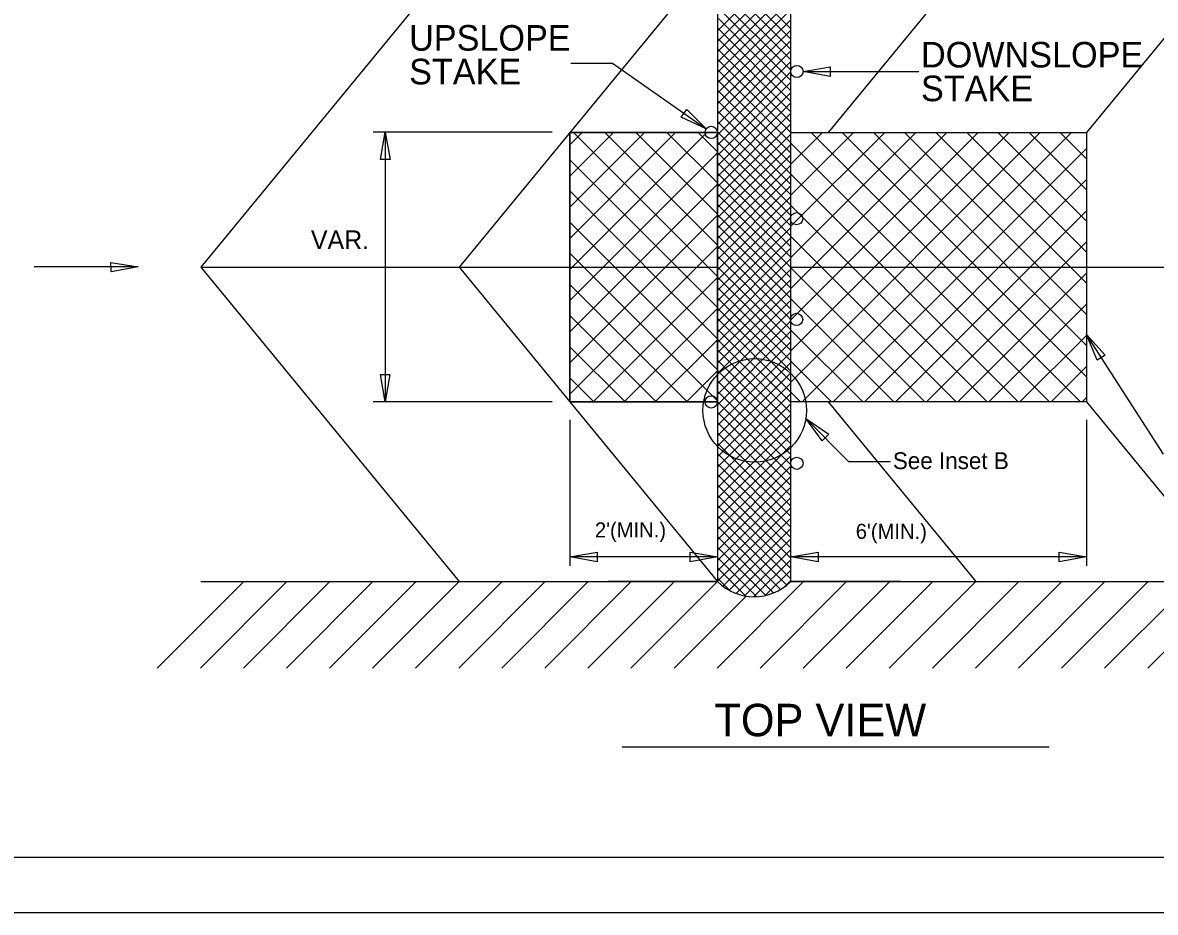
# Model space of a CAD drawing. Extents: x 8096 to 9796, y 9620 to 10720.
# Drawn here: x 9098.7 to 9561.9, y 9619.8 to 9983.4 of the extents above; entities that cross this region are included whole.
import ezdxf

# ---------------------------------------------------------------- set-up
doc = ezdxf.new("R2010")
doc.units = 0
for name, color, linetype in [('Blank Plan Sheet Both CELL', 7, 'Continuous'), ('Default', 7, 'Continuous'), ('Old_Level_1', 7, 'Continuous'), ('Old_Level_2', 7, 'Continuous'), ('Old_Level_20', 7, 'Continuous'), ('Sheet Plot Border Outside CELL', 7, 'Continuous')]:
    doc.layers.add(name, color=color, linetype=linetype)

msp = doc.modelspace()

# ---------------------------------------------------------------- linework, layer by layer
at = {"layer": 'Blank Plan Sheet Both CELL'}
msp.add_lwpolyline([(9762.02, 10692.33), (8262.02, 10692.33), (8262.02, 9642.33), (9762.02, 9642.33)], close=True, dxfattribs=at)
at = {"layer": 'Default'}
for p, q in [((9382.84, 10011.98), (9382.84, 9754.98)), ((9382.84, 10010.95), (9412.86, 9980.94)), ((9382.84, 9979.99), (9412.86, 10010)), ((9412.86, 9754.98), (9412.86, 10011.98)), ((9382.84, 10006.71), (9412.86, 9976.69)), ((9382.84, 9975.74), (9412.86, 10005.76)), ((9382.84, 10002.46), (9412.86, 9972.45)), ((9382.84, 9971.5), (9412.86, 10001.51)), ((9382.84, 9998.22), (9412.86, 9968.21)), ((9382.84, 9967.26), (9412.86, 9997.27)), ((9382.84, 9993.98), (9412.86, 9963.97)), ((9382.84, 9963.02), (9412.86, 9993.03)), ((9382.84, 9989.73), (9412.86, 9959.72)), ((9382.84, 9958.77), (9412.86, 9988.79)), ((9382.84, 9985.49), (9412.86, 9955.48)), ((9382.84, 9954.53), (9412.86, 9984.54)), ((9382.84, 9981.25), (9412.86, 9951.24)), ((9382.84, 9950.29), (9412.86, 9980.3)), ((9382.84, 9977.01), (9412.86, 9946.99)), ((9382.84, 9946.05), (9412.86, 9976.06)), ((9382.84, 9972.76), (9412.86, 9942.75)), ((9382.84, 9941.8), (9412.86, 9971.82)), ((9382.84, 9968.52), (9412.86, 9938.51)), ((9382.84, 9937.56), (9412.86, 9967.57)), ((9382.84, 9964.28), (9412.86, 9934.27)), ((9382.84, 9933.32), (9412.86, 9963.33)), ((9382.84, 9960.04), (9412.86, 9930.02)), ((9382.84, 9929.07), (9412.86, 9959.09)), ((9382.84, 9955.79), (9412.86, 9925.78)), ((9382.84, 9924.83), (9412.86, 9954.84)), ((9382.84, 9951.55), (9412.86, 9921.54)), ((9382.84, 9920.59), (9412.86, 9950.6)), ((9382.84, 9947.31), (9412.86, 9917.3)), ((9382.84, 9916.35), (9412.86, 9946.36)), ((9382.84, 9943.07), (9412.86, 9913.05)), ((9382.84, 9912.1), (9412.86, 9942.12)), ((9322.47, 9828.41), (9322.47, 9938.55)), ((9322.47, 9938.55), (9382.84, 9938.55)), ((9322.47, 9828.41), (9322.47, 9938.55)), ((9322.47, 9938.55), (9322.47, 9828.41)), ((9382.84, 9938.55), (9322.47, 9938.55)), ((9322.47, 9938.55), (9322.47, 9828.41)), ((9322.47, 9933.44), (9327.58, 9938.55)), ((9322.47, 9920.71), (9340.31, 9938.55)), ((9322.47, 9907.99), (9353.04, 9938.55)), ((9322.47, 9895.26), (9365.76, 9938.55)), ((9322.47, 9882.53), (9378.49, 9938.55)), ((9324.01, 9938.55), (9382.84, 9879.72)), ((9336.74, 9938.55), (9382.84, 9892.45)), ((9349.47, 9938.55), (9382.84, 9905.17)), ((9362.2, 9938.55), (9382.84, 9917.9)), ((9374.92, 9938.55), (9382.84, 9930.63)), ((9382.84, 9938.82), (9412.86, 9908.81)), ((9382.84, 9828.41), (9382.84, 9938.55)), ((9382.84, 9907.86), (9412.86, 9937.87)), ((9412.86, 9938.55), (9533.77, 9938.55)), ((9412.86, 9828.41), (9412.86, 9938.55)), ((9412.86, 9938.55), (9533.77, 9938.55)), ((9412.86, 9938.35), (9413.05, 9938.55)), ((9412.86, 9925.63), (9425.78, 9938.55)), ((9412.86, 9912.9), (9438.51, 9938.55)), ((9412.86, 9900.17), (9451.24, 9938.55)), ((9412.86, 9887.44), (9463.96, 9938.55)), ((9412.86, 9874.71), (9476.69, 9938.55)), ((9412.86, 9861.99), (9489.42, 9938.55)), ((9412.86, 9849.26), (9502.15, 9938.55)), ((9412.86, 9836.53), (9514.87, 9938.55)), ((9417.46, 9828.41), (9527.6, 9938.55)), ((9421.2, 9938.55), (9531.34, 9828.41)), ((9433.92, 9938.55), (9533.77, 9838.7)), ((9446.65, 9938.55), (9533.77, 9851.43)), ((9459.38, 9938.55), (9533.77, 9864.16)), ((9472.11, 9938.55), (9533.77, 9876.89)), ((9484.84, 9938.55), (9533.77, 9889.62)), ((9497.56, 9938.55), (9533.77, 9902.34)), ((9510.29, 9938.55), (9533.77, 9915.07)), ((9523.02, 9938.55), (9533.77, 9927.8)), ((9533.77, 9938.55), (9533.77, 9828.41)), ((9533.77, 9938.55), (9533.77, 9828.41)), ((9382.84, 9934.58), (9412.86, 9904.57)), ((9382.84, 9903.62), (9412.86, 9933.63)), ((9412.86, 9934.16), (9518.61, 9828.41)), ((9430.19, 9828.41), (9533.77, 9931.99)), ((9322.47, 9869.8), (9382.84, 9930.17)), ((9322.47, 9927.36), (9382.84, 9866.99)), ((9382.84, 9930.34), (9412.86, 9900.33)), ((9382.84, 9899.38), (9412.86, 9929.39)), ((9382.84, 9926.1), (9412.86, 9896.08)), ((9382.84, 9895.13), (9412.86, 9925.15)), ((9382.84, 9921.85), (9412.86, 9891.84)), ((9412.86, 9921.44), (9505.88, 9828.41)), ((9322.47, 9857.07), (9382.84, 9917.44)), ((9382.84, 9890.89), (9412.86, 9920.9)), ((9382.84, 9917.61), (9412.86, 9887.6)), ((9442.92, 9828.41), (9533.77, 9919.26)), ((9322.47, 9914.63), (9382.84, 9854.26)), ((9382.84, 9886.65), (9412.86, 9916.66)), ((9382.84, 9913.37), (9412.86, 9883.36)), ((9382.84, 9882.41), (9412.86, 9912.42)), ((9382.84, 9909.12), (9412.86, 9879.11)), ((9382.84, 9878.16), (9412.86, 9908.18)), ((9412.86, 9908.71), (9493.16, 9828.41)), ((9322.47, 9844.35), (9382.84, 9904.72)), ((9382.84, 9904.88), (9412.86, 9874.87)), ((9382.84, 9873.92), (9412.86, 9903.93)), ((9455.64, 9828.41), (9533.77, 9906.53)), ((9322.47, 9901.91), (9382.84, 9841.53)), ((9382.84, 9900.64), (9412.86, 9870.63)), ((9382.84, 9869.68), (9412.86, 9899.69)), ((9382.84, 9896.4), (9412.86, 9866.38)), ((9382.84, 9865.44), (9412.86, 9895.45)), ((9412.86, 9895.98), (9480.43, 9828.41)), ((9468.37, 9828.41), (9533.77, 9893.81)), ((9322.47, 9831.62), (9382.84, 9891.99)), ((9322.47, 9889.18), (9382.84, 9828.81)), ((9382.84, 9892.15), (9412.86, 9862.14)), ((9382.84, 9861.19), (9412.86, 9891.2)), ((9382.84, 9887.91), (9412.86, 9857.9)), ((9382.84, 9856.95), (9412.86, 9886.96)), ((9382.84, 9883.67), (9412.86, 9853.66)), ((9382.84, 9852.71), (9412.86, 9882.72)), ((9412.86, 9883.25), (9467.7, 9828.41)), ((9481.1, 9828.41), (9533.77, 9881.08)), ((9322.47, 9876.45), (9370.52, 9828.41)), ((9331.99, 9828.41), (9382.84, 9879.26)), ((9382.84, 9879.43), (9412.86, 9849.41)), ((9382.84, 9848.46), (9412.86, 9878.48)), ((9382.84, 9875.18), (9412.86, 9845.17)), ((9382.84, 9844.22), (9412.86, 9874.23)), ((9382.84, 9870.94), (9412.86, 9840.93)), ((9412.86, 9870.52), (9454.97, 9828.41)), ((9344.72, 9828.41), (9382.84, 9866.53)), ((9382.84, 9839.98), (9412.86, 9869.99)), ((9382.84, 9866.7), (9412.86, 9836.69)), ((9382.84, 9835.74), (9412.86, 9865.75)), ((9493.83, 9828.41), (9533.77, 9868.35)), ((9322.47, 9863.72), (9357.79, 9828.41)), ((9382.84, 9862.46), (9412.86, 9832.44)), ((9382.84, 9831.49), (9412.86, 9861.51)), ((9382.84, 9858.21), (9412.86, 9828.2)), ((9382.84, 9827.25), (9412.86, 9857.26)), ((9412.86, 9857.8), (9442.24, 9828.41)), ((9357.44, 9828.41), (9382.84, 9853.81)), ((9382.84, 9853.97), (9412.86, 9823.96)), ((9382.84, 9823.01), (9412.86, 9853.02)), ((9506.56, 9828.41), (9533.77, 9855.62)), ((9322.47, 9850.99), (9345.06, 9828.41)), ((9382.84, 9849.73), (9412.86, 9819.72)), ((9382.84, 9818.77), (9412.86, 9848.78)), ((9382.84, 9845.49), (9412.86, 9815.47)), ((9382.84, 9814.52), (9412.86, 9844.54)), ((9412.86, 9845.07), (9429.52, 9828.41)), ((9519.28, 9828.41), (9533.77, 9842.89)), ((9322.47, 9838.27), (9332.33, 9828.41)), ((9370.17, 9828.41), (9382.84, 9841.08)), ((9382.84, 9841.24), (9412.86, 9811.23)), ((9382.84, 9810.28), (9412.86, 9840.29)), ((9382.84, 9837), (9412.86, 9806.99)), ((9382.84, 9806.04), (9412.86, 9836.05)), ((9382.84, 9832.76), (9412.86, 9802.74)), ((9382.84, 9801.8), (9412.86, 9831.81)), ((9412.86, 9832.34), (9416.79, 9828.41)), ((9532.01, 9828.41), (9533.77, 9830.17)), ((9382.84, 9828.41), (9322.47, 9828.41)), ((9322.47, 9828.41), (9382.84, 9828.41)), ((9382.84, 9828.51), (9412.86, 9798.5)), ((9382.84, 9797.55), (9412.86, 9827.57)), ((9382.84, 9824.27), (9412.86, 9794.26)), ((9533.77, 9828.41), (9412.86, 9828.41)), ((9533.77, 9828.41), (9412.86, 9828.41)), ((9382.84, 9793.31), (9412.86, 9823.32)), ((9382.84, 9820.03), (9412.86, 9790.02)), ((9382.84, 9789.07), (9412.86, 9819.08)), ((9382.84, 9815.79), (9412.86, 9785.77)), ((9382.84, 9784.83), (9412.86, 9814.84)), ((9382.84, 9811.54), (9412.86, 9781.53)), ((9382.84, 9780.58), (9412.86, 9810.59)), ((9382.84, 9807.3), (9412.86, 9777.29)), ((9382.84, 9776.34), (9412.86, 9806.35)), ((9382.84, 9803.06), (9412.86, 9773.05)), ((9382.84, 9772.1), (9412.86, 9802.11)), ((9382.84, 9798.82), (9412.86, 9768.8)), ((9382.84, 9767.85), (9412.86, 9797.87)), ((9382.84, 9794.57), (9412.86, 9764.56)), ((9382.84, 9763.61), (9412.86, 9793.62)), ((9382.84, 9790.33), (9412.86, 9760.32)), ((9382.84, 9759.37), (9412.86, 9789.38)), ((9382.84, 9786.09), (9412.86, 9756.08)), ((9382.84, 9755.13), (9412.86, 9785.14)), ((9382.84, 9781.85), (9411.17, 9753.52)), ((9385.06, 9753.11), (9412.86, 9780.9)), ((9382.84, 9777.6), (9408.65, 9751.79)), ((9382.84, 9773.36), (9405.82, 9750.38)), ((9387.65, 9751.45), (9412.86, 9776.65)), ((9382.84, 9769.12), (9402.57, 9749.39)), ((9390.57, 9750.12), (9412.86, 9772.41)), ((9382.84, 9764.87), (9398.84, 9748.88)), ((9393.92, 9749.23), (9412.86, 9768.17)), ((9397.79, 9748.86), (9412.86, 9763.93)), ((9382.84, 9760.63), (9394.32, 9749.15)), ((9402.57, 9749.39), (9412.86, 9759.68)), ((9189.15, 9754.98), (9153.8, 9719.62)), ((9206.76, 9754.98), (9171.41, 9719.62)), ((9224.37, 9754.98), (9189.01, 9719.62)), ((9241.98, 9754.98), (9206.62, 9719.62)), ((9259.59, 9754.98), (9224.23, 9719.62)), ((9277.19, 9754.98), (9241.84, 9719.62)), ((9294.8, 9754.98), (9259.45, 9719.62)), ((9312.41, 9754.98), (9277.05, 9719.62)), ((9330.02, 9754.98), (9294.66, 9719.62)), ((9347.63, 9754.98), (9312.27, 9719.62)), ((9365.23, 9754.98), (9329.88, 9719.62)), ((9382.84, 9754.98), (9347.49, 9719.62)), ((9418.06, 9754.98), (9382.7, 9719.62)), ((9382.84, 9756.39), (9387.94, 9751.29)), ((9435.67, 9754.98), (9400.31, 9719.62)), ((9410.17, 9752.76), (9412.86, 9755.44)), ((9453.28, 9754.98), (9417.92, 9719.62)), ((9470.88, 9754.98), (9435.53, 9719.62)), ((9488.49, 9754.98), (9453.14, 9719.62)), ((9506.1, 9754.98), (9470.75, 9719.62)), ((9523.71, 9754.98), (9488.35, 9719.62)), ((9541.32, 9754.98), (9505.96, 9719.62)), ((9558.93, 9754.98), (9523.57, 9719.62)), ((9576.53, 9754.98), (9541.18, 9719.62)), ((9594.14, 9754.98), (9558.79, 9719.62)), ((9394.56, 9749.09), (9365.1, 9719.62))]:
    msp.add_line(p, q, dxfattribs=at)
for points in [[(9277.19, 10011.98), (9171.54, 9883.48), (9277.19, 9754.98)], [(9382.84, 10011.98), (9277.19, 9883.48), (9382.84, 9754.98)], [(9488.49, 10011.98), (9428.12, 9938.55)], [(9594.14, 10011.98), (9533.77, 9938.55)], [(9428.12, 9828.41), (9488.49, 9754.98)], [(9533.77, 9828.41), (9594.14, 9754.98)]]:
    msp.add_lwpolyline(points, dxfattribs=at)
for centre, radius in [((9415.35, 9963.43), 2.5), ((9380.34, 9938.55), 2.5), ((9415.23, 9903.29), 2.5), ((9415.23, 9862.12), 2.5), ((9398.1, 9824.94), 21.16), ((9380.34, 9828.41), 2.5), ((9415.35, 9803.32), 2.5)]:
    msp.add_circle(centre, radius, dxfattribs=at)
msp.add_arc((9397.85, 9770.24), 21.41, 225.4932, 314.5068, dxfattribs=at)
at = {"layer": 'Old_Level_1'}
for p, q in [((9322.84, 9966.83), (9339.98, 9966.83)), ((9417.85, 9963.43), (9465.21, 9963.43)), ((9315.22, 9938.64), (9242.01, 9938.64)), ((9247.01, 9938.64), (9247.01, 9828.41)), ((9146, 9883.55), (9103.43, 9883.66)), ((9171.54, 9883.48), (9382.84, 9883.48)), ((9412.86, 9883.48), (9699.79, 9883.48)), ((9565.31, 9807.04), (9533.77, 9855.94)), ((9315.22, 9828.41), (9242.01, 9828.41)), ((9322.47, 9821.16), (9322.47, 9761.37)), ((9533.8, 9821.16), (9533.8, 9761.37)), ((9436.44, 9804.09), (9453.57, 9804.09)), ((9382.84, 9765.06), (9322.47, 9765.06)), ((9533.8, 9765.06), (9412.86, 9765.06)), ((9171.54, 9754.98), (9382.84, 9754.98)), ((9382.84, 9755.09), (9338.2, 9755.09)), ((9457.67, 9755.09), (9412.86, 9755.09)), ((9412.86, 9754.98), (9699.79, 9754.98))]:
    msp.add_line(p, q, dxfattribs=at)
at = {"layer": 'Old_Level_2'}
for p, q in [((9339.98, 9966.83), (9378.3, 9939.98)), ((9419.01, 9821.63), (9436.44, 9804.09))]:
    msp.add_line(p, q, dxfattribs=at)
for points in [[(9417.85, 9963.43), (9429, 9965.35), (9429, 9961.46)], [(9378.3, 9939.98), (9368.04, 9944.78), (9370.28, 9947.97)], [(9247.01, 9938.64), (9248.98, 9927.48), (9245.09, 9927.48)], [(9146, 9883.55), (9134.91, 9881.52), (9134.85, 9885.41)], [(9533.77, 9855.94), (9541.38, 9847.58), (9538.12, 9845.51)], [(9247.01, 9828.41), (9245.03, 9839.56), (9248.92, 9839.56)], [(9419, 9821.63), (9428.34, 9815.25), (9425.63, 9812.45)], [(9322.47, 9765.06), (9333.62, 9766.98), (9333.62, 9763.09)], [(9382.84, 9765.06), (9371.68, 9763.09), (9371.68, 9766.98)], [(9412.86, 9765.06), (9424.01, 9766.98), (9424.01, 9763.09)], [(9533.8, 9765.06), (9522.65, 9763.09), (9522.65, 9766.98)]]:
    msp.add_lwpolyline(points, close=True, dxfattribs=at)
at = {"layer": 'Old_Level_20'}
msp.add_line((9343.84, 9687.44), (9518.54, 9687.44), dxfattribs=at)
at = {"layer": 'Sheet Plot Border Outside CELL'}
msp.add_lwpolyline([(8095.52, 9619.83), (9795.52, 9619.83), (9795.52, 10719.83), (8095.52, 10719.83)], close=True, dxfattribs=at)

# ---------------------------------------------------------------- texts
at = {"layer": 'Old_Level_1'}
for s, height, p in [('UPSLOPE', 10.454, (9256.78, 9971.95)), ('DOWNSLOPE', 10.454, (9466.09, 9965.08)), ('STAKE', 10.454, (9256.78, 9958.18)), ('STAKE', 10.454, (9466.09, 9951.31)), ('VAR.', 7.621, (9216.62, 9890.86)), ('See Inset B', 6.8591, (9454.58, 9800.97)), ("2'(MIN.)", 6.173, (9332.75, 9773.01)), ("6'(MIN.)", 6.173, (9439.41, 9772.45)), ('TOP VIEW', 13.242, (9381.62, 9691.8))]:
    msp.add_text(s, height=height, dxfattribs=at).set_placement(p)

doc.saveas('drawing.dxf')
